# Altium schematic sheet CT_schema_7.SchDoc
size 278 x 170 mm
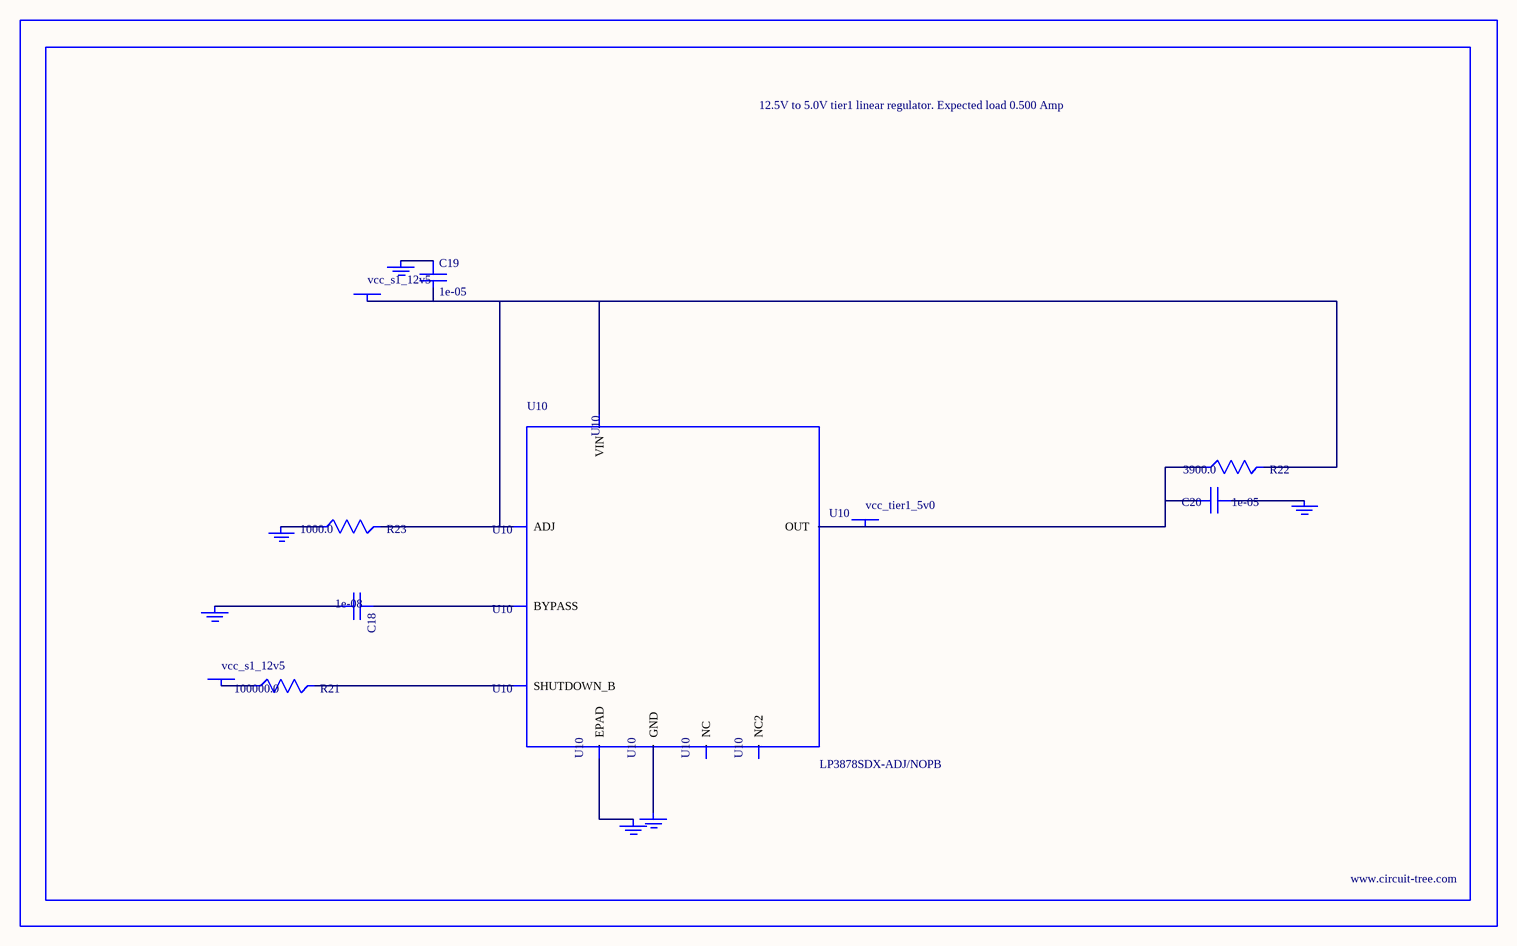
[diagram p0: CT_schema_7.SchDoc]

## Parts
BORDER6  (no value)
C18  1e-08  [C0402]
C19  1e-05  [C1210]
C20  1e-05  [C1210]
GND_INSTANCE_6_0  (no value)
GND_INSTANCE_6_1  (no value)
GND_INSTANCE_6_2  (no value)
GND_INSTANCE_6_3  (no value)
GND_INSTANCE_6_4  (no value)
GND_INSTANCE_6_5  (no value)
POWER_INSTANCE_6_0  vcc_s1_12v5
POWER_INSTANCE_6_1  vcc_s1_12v5
POWER_INSTANCE_6_2  vcc_tier1_5v0
R21  100000.0  [R0603]
R22  3900.0  [R0603]
R23  1000.0  [R0603]
U10  LP3878SDX-ADJ/NOPB  [WSON-8]

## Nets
NetC18_1: C18.1 U10.1(BYPASS)
NetC18_2: C18.2 GND_INSTANCE_6_0.0(GND)
NetC19_1: C19.1 GND_INSTANCE_6_1.0(GND)
NetC19_2: C19.2 POWER_INSTANCE_6_0.0(PWR) R22.2 R23.2 U10.4(VIN) U10.6(ADJ)
NetC20_1: C20.1 GND_INSTANCE_6_2.0(GND)
NetC20_2: C20.2 POWER_INSTANCE_6_2.0(PWR) R22.1 U10.5(OUT)
NetGND_INSTANCE_6_3_0: GND_INSTANCE_6_3.0(GND) R23.1
NetGND_INSTANCE_6_4_0: GND_INSTANCE_6_4.0(GND) U10.PAD(EPAD)
NetGND_INSTANCE_6_5_0: GND_INSTANCE_6_5.0(GND) U10.3(GND)
NetPOWER_INSTANCE_6_1_0: POWER_INSTANCE_6_1.0(PWR) R21.1
NetR21_2: R21.2 U10.8(SHUTDOWN_B)

Not connected (* = marked no-connect by the designer): U10 2(NC) 7(NC2)

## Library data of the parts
BORDER6 = BORDER_PAGE6
C18 = C0402C103K3RAC
C19 = C1210C106K5PACTU
C20 = GRM32DR61E106MA12L
GND_INSTANCE_6_0-GND_INSTANCE_6_5 = GND
POWER_INSTANCE_6_0-POWER_INSTANCE_6_2 = PWR
R21 = RC0603JR-07100KL
R22 = RC0603JR-073K9L
R23 = RC0603JR-071KL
